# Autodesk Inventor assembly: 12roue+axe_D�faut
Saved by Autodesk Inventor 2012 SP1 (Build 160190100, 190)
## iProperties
Created: 2011-01
Part Number: 12roue+axe_D�faut
Document SubType Name: Assembly
Designer: eric
Mass: 62.4241 g
Surface Area: 248.334 cm^2
Volume: 62.4241 cm^3
Density: 1 g/cm^3
Author: eric
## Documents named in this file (3)
- I:\TSsi\EDT TDP\chariot_de_golf\chariot_de_golf_trolem\12roue+axe_Defaut.iam
- I:\TSsi\EDT TDP\chariot_de_golf\chariot_de_golf_trolem\12axe-roue-helicoidale_Defaut.ipt
- I:\TSsi\EDT TDP\chariot_de_golf\chariot_de_golf_trolem\12Roue helicoidale_Defaut.ipt
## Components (2 placed, 2 different names)
1. 12axe-roue-helicoidale_Defaut:1
2. 12Roue helicoidale_Defaut:1
